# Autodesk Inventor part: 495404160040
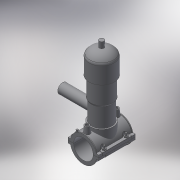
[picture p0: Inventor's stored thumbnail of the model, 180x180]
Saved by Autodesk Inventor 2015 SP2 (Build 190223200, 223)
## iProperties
Created: 2017-07
Part Number: 495404160040
Material: Generic
Description: PLASSON TAPPING VALVE 160-40
Document SubType Name: Modeling
Designer: KIM
Density: 1 g/cm^3
Appearance: Default
Author: KIM
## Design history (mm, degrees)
derived "495404-4954S4.ipt"
feature "Solid1::495404-4954S4.ipt"
feature "Solid2::495404-4954S4.ipt"
tag "TaggingFeature1"
body "Solid1"
body "Solid2"
other parameters: "d2" = 202, "d4" = 118, "d5" = 0, "d6" = 0.1, "d8" = 0, "d19" = 6, "d20" = 6, "d21" = 70.8, "d23" = 0, "d24" = 35.4, "d26" = 0, "d27" = 3, "d28" = 3, "d29" = 3, "d30" = 53.33333, "d31" = 6, "d32" = 0, "d33" = 0, "d34" = 0.6, "d40" = 99.84, "d47" = 142, "d70" = 15, "d72" = 0, "d73" = 6, "d75" = 5, "d76" = 0, "d77" = 8, "d79" = 15, "d80" = 47.2, "d82" = 5 deg, "d84" = 4, "d85" = 14, "d86" = 0, "d87" = 3, "d88" = 0, "d89" = 1, "d90" = 1, "d91" = 94.4, "d92" = 0, "d93" = 0.5, "d94" = 84.21053, "d96" = 197.76, "d97" = 2.36, "d98" = 0, "d120" = 140 deg, "d121" = 24.228, "d122" = 20 deg, "d123" = 384, "d124" = 115.2, "d126" = 0, "d143" = 164.8, "d145" = 24.61538, "d149" = 2.4, "d150" = 27.07692, "d153" = 118, "d154" = 0, "d156" = 96, "d157" = 160 deg, "d159" = 6.4, "d161" = 2.4, "d162" = 70.8, "d163" = 0, "d167" = 16, "d168" = 93.65854, "d170" = 3, "d172" = 0, "d173" = 1, "d176" = 20 deg, "d177" = 11.2, "d178" = 32, "d180" = 0, "d183" = 12.8, "d184" = 8.96, "d185" = 38.35, "d186" = 38.35, "d187" = 96, "d188" = 9.6, "d189" = 11.2, "d190" = 0, "d191" = 144, "d193" = 6.8, "d194" = 2.95, "d195" = 90 deg, "d197" = 0, "d199" = 0, "d205" = 14.64, "d206" = 81.33333, "d207" = 244, "d208" = 224.48, "d209" = 207.4, "d210" = 200.08, "d211" = 146.4, "d212" = 85.4, "d213" = 65.88, "d214" = 73.2, "d216" = 19.52, "d217" = 70.76, "d218" = 80.52, "d222" = 0, "d223" = 192, "d224" = 137, "d225" = 46, "d229" = 137, "d230" = 0, "B_" = 202, "H_" = 137, "L_" = 118, "d_t" = 6, "H_1" = 46, "H_2" = 244, "d148" = 2.4, "d160" = 2.4, "d169" = 3, "d192" = 6.8, "d228" = 32
